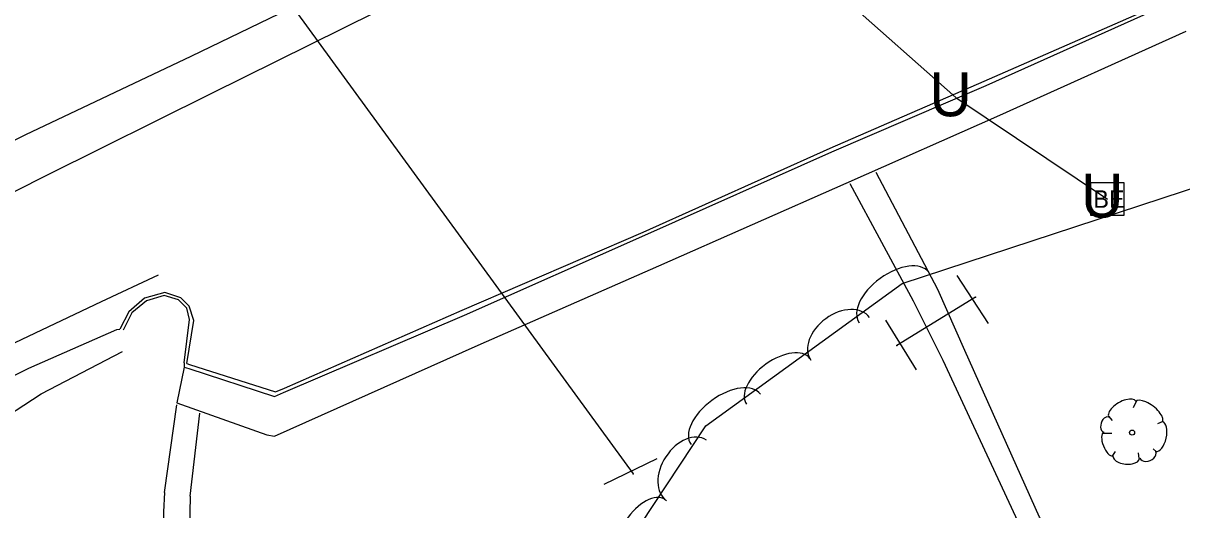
# Model space of a CAD drawing. Extents: x 1042086 to 1119166, y 1916606 to 1927565.
# Drawn here: x 1042673.9 to 1042832.5, y 1926194.2 to 1926260.8 of the extents above; entities that cross this region are included whole.
import ezdxf

# ---------------------------------------------------------------- set-up
doc = ezdxf.new("R2010")
doc.units = 0
for name, color, linetype in [('Default', 7, 'Continuous'), ('S_CROSS_DRAIN', 7, 'Continuous'), ('S_CURB', 7, 'Continuous'), ('S_DRG_PT_SYM', 7, 'Continuous'), ('S_EDGE_PAVEMENT', 7, 'Continuous'), ('S_ELECTRIC_UTILITIES', 7, 'Continuous'), ('S_GRAVEL_ROAD', 7, 'Continuous'), ('S_HEADWALL', 7, 'Continuous'), ('S_SHOULDER', 7, 'Continuous'), ('S_SIDE_DRAIN', 7, 'Continuous'), ('S_SIDEWALK', 7, 'Continuous'), ('S_TREE', 7, 'Continuous'), ('S_UNDERGROUND_CABLE', 7, 'Continuous')]:
    doc.layers.add(name, color=color, linetype=linetype)

msp = doc.modelspace()

# ---------------------------------------------------------------- linework, layer by layer
at = {"layer": 'S_CROSS_DRAIN'}
msp.add_line((1042695.76, 1926283.73), (1042757.39, 1926199.15), dxfattribs=at)
at = {"layer": 'S_CURB'}
for points in [[(1042695.94, 1926214.35), (1042695.97, 1926213.78), (1042696.59, 1926213.58), (1042708.32, 1926209.73), (1042709.56, 1926210.3), (1042734.31, 1926220.89), (1042758.98, 1926231.82), (1042784.56, 1926243.21), (1042805.68, 1926252.32), (1042831.22, 1926263.78), (1042854.05, 1926273.96)], [(1042695.94, 1926214.35), (1042696.71, 1926220.3), (1042696.34, 1926221.85), (1042695.2, 1926222.99), (1042693.23, 1926223.57), (1042690.82, 1926222.82), (1042688.82, 1926221.2), (1042687.61, 1926218.84)]]:
    msp.add_lwpolyline(points, dxfattribs=at)
at = {"layer": 'S_DRG_PT_SYM'}
for points in [[(1042804.22, 1926223.34), (1042804.22, 1926223.39), (1042804.22, 1926223.34), (1042804.17, 1926223.34), (1042804.22, 1926223.34), (1042804.22, 1926223.29), (1042804.22, 1926223.34), (1042804.27, 1926223.34)], [(1042793.47, 1926216.71), (1042793.47, 1926216.76), (1042793.47, 1926216.71), (1042793.42, 1926216.71), (1042793.47, 1926216.71), (1042793.47, 1926216.66), (1042793.47, 1926216.71), (1042793.52, 1926216.71)], [(1042757.39, 1926199.15), (1042757.39, 1926199.2), (1042757.39, 1926199.15), (1042757.34, 1926199.15), (1042757.39, 1926199.15), (1042757.39, 1926199.1), (1042757.39, 1926199.15), (1042757.44, 1926199.15)]]:
    msp.add_lwpolyline(points, dxfattribs=at)
at = {"layer": 'S_EDGE_PAVEMENT'}
for points in [[(1042478.4, 1926119.04), (1042498.1, 1926134.43), (1042518.07, 1926149.47), (1042540.9, 1926165.27), (1042560.98, 1926178.59), (1042584.41, 1926192.02), (1042606.45, 1926203.82), (1042610.43, 1926206.01), (1042632.63, 1926217.51), (1042654.93, 1926228.83), (1042677.26, 1926240.1), (1042699.67, 1926251.2), (1042722.25, 1926262.4), (1042744.82, 1926273.18), (1042760.77, 1926281), (1042763.22, 1926282.13), (1042768.77, 1926285)], [(1042696.32, 1926214.25), (1042696.7, 1926214.11), (1042708.44, 1926210.37), (1042709.68, 1926210.89), (1042734, 1926221.56), (1042758.78, 1926232.26), (1042784.32, 1926243.73), (1042805.41, 1926252.91), (1042831.04, 1926264.16), (1042853.86, 1926274.37)], [(1042314.98, 1925946.56), (1042333.03, 1925963.86), (1042351.17, 1925981.07), (1042369.3, 1925998.28), (1042387.55, 1926015.37), (1042405.76, 1926032.5), (1042426.42, 1926051.4), (1042444.97, 1926068.17), (1042463.5, 1926083.92), (1042482.82, 1926099.8), (1042502.5, 1926115.23), (1042522.45, 1926130.28), (1042543.09, 1926144.46), (1042563.17, 1926157.16), (1042584.61, 1926170.06), (1042606.22, 1926182.66), (1042628.21, 1926194.55), (1042650.36, 1926206.15), (1042672.85, 1926217.12), (1042684.66, 1926222.76), (1042692.45, 1926226.41)], [(1042696.32, 1926214.25), (1042697.3, 1926220.14), (1042696.66, 1926222.11), (1042695.52, 1926223.25), (1042693.3, 1926224), (1042690.54, 1926223.2), (1042688.38, 1926221.34), (1042687.17, 1926218.97)]]:
    msp.add_lwpolyline(points, dxfattribs=at)
at = {"layer": 'S_ELECTRIC_UTILITIES'}
msp.add_lwpolyline([(1042820.02, 1926234.52), (1042820.02, 1926239.02), (1042824.52, 1926239.02), (1042824.52, 1926234.52)], close=True, dxfattribs=at)
at = {"layer": 'S_GRAVEL_ROAD'}
msp.add_lwpolyline([(1042320.92, 1925940.27), (1042339, 1925957.53), (1042357.41, 1925974.4), (1042375.92, 1925991.21), (1042394.15, 1926008.36), (1042412.58, 1926025.21), (1042430.86, 1926042.33), (1042449.27, 1926059.03), (1042468.47, 1926074.87), (1042488.22, 1926089.86), (1042508.69, 1926104.43), (1042528.93, 1926118.62), (1042549.12, 1926132.48), (1042569.74, 1926146.19), (1042591.11, 1926158.73), (1042613.27, 1926170.19), (1042634.47, 1926182.83), (1042655.44, 1926196.45), (1042676.41, 1926210.11), (1042687.51, 1926215.92)], dxfattribs=at)
at = {"layer": 'S_HEADWALL'}
for points in [[(1042806.01, 1926219.75), (1042801.71, 1926226.31)], [(1042796.16, 1926213.41), (1042791.96, 1926220.19)], [(1042753.42, 1926197.77), (1042760.69, 1926201.27)]]:
    msp.add_lwpolyline(points, dxfattribs=at)
at = {"layer": 'S_SHOULDER'}
for points in [[(1042607.52, 1926211.41), (1042629.65, 1926223.03), (1042651.94, 1926234.38), (1042674.28, 1926245.62), (1042696.91, 1926256.32), (1042719.69, 1926267.36), (1042742.62, 1926277.43), (1042759.24, 1926283.96)], [(1042317.8, 1925943.58), (1042335.98, 1925960.74), (1042354.18, 1925977.88), (1042372.5, 1925994.89), (1042390.71, 1926012.02), (1042409.03, 1926029.04), (1042429.36, 1926048.29), (1042447.98, 1926064.98), (1042466.11, 1926080.54), (1042485.65, 1926096.14), (1042505.02, 1926111.95), (1042524.95, 1926127.05), (1042545.73, 1926141.05), (1042565.19, 1926153.4), (1042586.67, 1926166.25), (1042608.26, 1926178.89), (1042630.25, 1926190.77), (1042652.38, 1926202.41), (1042674.73, 1926213.63), (1042686.73, 1926218.92), (1042687.17, 1926218.97)]]:
    msp.add_lwpolyline(points, dxfattribs=at)
at = {"layer": 'S_SIDE_DRAIN'}
msp.add_line((1042804.22, 1926223.34), (1042793.47, 1926216.71), dxfattribs=at)
at = {"layer": 'S_SIDEWALK'}
for points in [[(1042695.97, 1926213.78), (1042694.97, 1926208.87), (1042695.59, 1926208.65), (1042707.25, 1926204.5), (1042708.34, 1926204.3), (1042736.2, 1926216.77), (1042760.9, 1926227.65), (1042786.52, 1926238.95), (1042807.55, 1926248.25), (1042833.07, 1926259.74)], [(1042799.09, 1926224.37), (1042790.62, 1926240.42)], [(1042795.74, 1926222.81), (1042787.06, 1926238.87)], [(1042827.74, 1926169.99), (1042825.66, 1926171.79), (1042812.97, 1926193.22), (1042802.76, 1926216.04), (1042799.09, 1926224.37)], [(1042826.45, 1926167.92), (1042825.46, 1926168.58), (1042823.38, 1926170.39), (1042810.35, 1926192), (1042799.81, 1926214.67), (1042795.74, 1926222.81)], [(1042693.29, 1926196.6), (1042694.98, 1926208.59)], [(1042696.78, 1926196.1), (1042698.11, 1926207.45)], [(1042693.29, 1926196.6), (1042693.15, 1926193.97), (1042693.22, 1926185.1), (1042693.98, 1926171.1), (1042694.9, 1926168.19), (1042696.93, 1926162.19), (1042699.02, 1926160.2), (1042705.98, 1926148.38), (1042710.92, 1926139.66), (1042712.3, 1926136.16), (1042716.63, 1926116.9)], [(1042696.78, 1926196.1), (1042696.74, 1926193.87), (1042696.78, 1926185.48), (1042697.55, 1926171.48), (1042698.46, 1926168.57), (1042700.4, 1926163.8), (1042708.17, 1926149.53), (1042713.12, 1926140.79), (1042714.71, 1926136.7), (1042719.04, 1926117.44)]]:
    msp.add_lwpolyline(points, dxfattribs=at)
at = {"layer": 'S_TREE'}
for p, q in [((1042826.21, 1926209.06), (1042825.82, 1926208.2)), ((1042822.41, 1926207.04), (1042822.92, 1926206.46)), ((1042829.78, 1926206.27), (1042829.12, 1926205.99)), ((1042821.76, 1926204.72), (1042822.88, 1926204.72)), ((1042822.92, 1926201.54), (1042823.38, 1926202.24)), ((1042826.6, 1926201.27), (1042826.52, 1926202.04)), ((1042829, 1926202.16), (1042828.54, 1926202.58))]:
    msp.add_line(p, q, dxfattribs=at)
msp.add_lwpolyline([(1042748.64, 1926122.33), (1042720.18, 1926139.83), (1042699.44, 1926164.04), (1042719.94, 1926181.6), (1042738.88, 1926176.86), (1042753.11, 1926184.18), (1042767.34, 1926205.74), (1042794.19, 1926225.22), (1042841.56, 1926240.79), (1042867.31, 1926216.35), (1042861.06, 1926204.42), (1042884.64, 1926187.8), (1042886.03, 1926165.83), (1042862.57, 1926158.27), (1042844.1, 1926180.24), (1042823.77, 1926175.36), (1042797.4, 1926153.85), (1042775.32, 1926134.56), (1042758.8, 1926122.73)], close=True, dxfattribs=at)
msp.add_circle((1042825.65, 1926204.81), 0.341, dxfattribs=at)
for centre, major_axis, ratio, start_param, end_param in [((1042793.07, 1926223.3), (-4.75, -3.45), 0.55008, 3.141593, 6.283185), ((1042785.73, 1926217.65), (-4.01, -2.91), 0.685311, 3.141593, 6.283185), ((1042777.23, 1926211.82), (-4.33, -3.14), 0.540699, 3.141593, 6.283185), ((1042770.06, 1926206.61), (-4.75, -3.45), 0.55008, 3.141593, 6.283185), ((1042824.32, 1926208.01), (1.86, 1.08), 0.471018, 0, 3.141593), ((1042827.97, 1926207.69), (-1.81, 1.36), 0.405113, 3.141593, 6.283186), ((1042822.08, 1926205.9), (0.31, 1.03), 0.646762, 0, 3.141593), ((1042829.33, 1926204.28), (0.46, 2.04), 0.482994, 3.141593, 6.283185), ((1042764.7, 1926199.64), (-2.73, -4.14), 0.685311, 3.141593, 6.283185), ((1042822.39, 1926203.25), (-0.61, 1.6), 0.420543, 6.283185, 9.424777), ((1042827.81, 1926201.76), (1.09, 0.46), 0.711534, 3.141592, 6.283185), ((1042824.85, 1926201.47), (-1.83, 0.19), 0.529943, 0, 3.141593), ((1042758.81, 1926191.19), (-2.94, -4.46), 0.540699, 3.141593, 6.283185)]:
    msp.add_ellipse(centre, major_axis=major_axis, ratio=ratio, start_param=start_param, end_param=end_param, dxfattribs=at)
at = {"layer": 'S_UNDERGROUND_CABLE'}
for p, q in [((1042763.32, 1926284.54), (1042801.55, 1926250.65)), ((1042801.55, 1926250.65), (1042822.29, 1926236.77))]:
    msp.add_line(p, q, dxfattribs=at)

# ---------------------------------------------------------------- texts
at = {"layer": 'Default'}
for p in [(1042797.92, 1926248.1), (1042818.67, 1926234.23)]:
    msp.add_text('U', height=6, rotation=360, dxfattribs=at).set_placement(p)
at = {"layer": 'S_ELECTRIC_UTILITIES'}
msp.add_text('BE', height=2.4, rotation=360, dxfattribs=at).set_placement((1042820.34, 1926235.57))

doc.saveas('drawing.dxf')
